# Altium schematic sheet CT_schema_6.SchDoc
size 287 x 160 mm
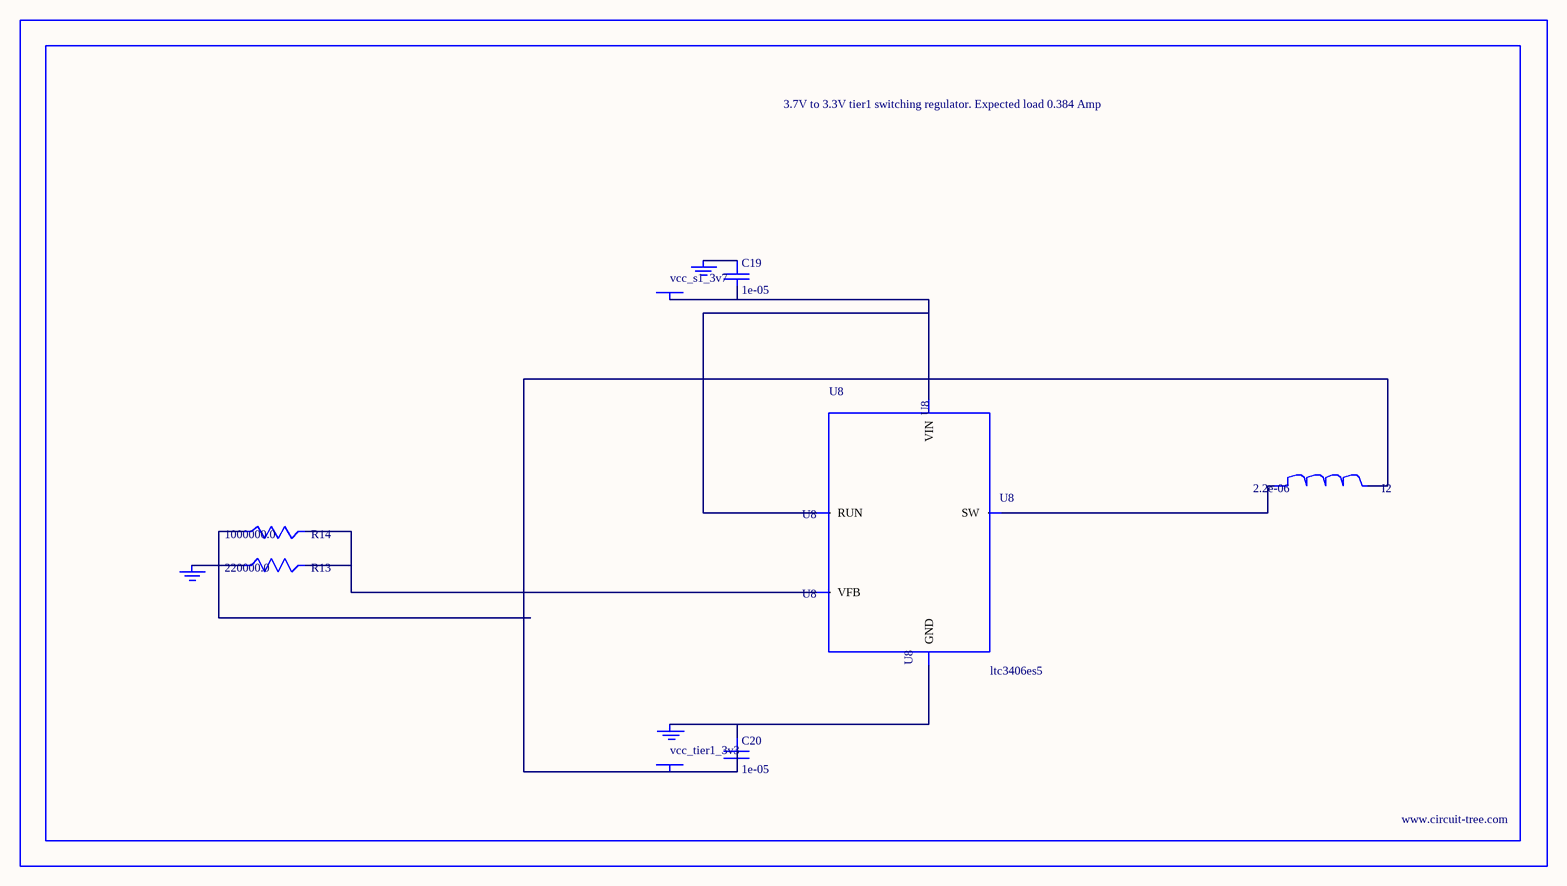
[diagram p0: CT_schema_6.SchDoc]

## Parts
BORDER5  (no value)
C19  1e-05  [C0805]
C20  1e-05  [C0805]
GND_INSTANCE_5_0  (no value)
GND_INSTANCE_5_1  (no value)
GND_INSTANCE_5_2  (no value)
I2  2.2e-06  [L0805]
POWER_INSTANCE_5_0  vcc_tier1_3v3
POWER_INSTANCE_5_1  vcc_s1_3v7
R13  220000.0  [R0603]
R14  1000000.0  [R0603]
U8  ltc3406es5  [TSOT-23-5]

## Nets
NetC19_1: C19.1 GND_INSTANCE_5_1.0(GND)
NetC19_2: C19.2 POWER_INSTANCE_5_1.0(PWR) U8.1(RUN) U8.4(VIN)
NetC20_1: C20.1 GND_INSTANCE_5_0.0(GND) U8.2(GND)
NetC20_2: C20.2 I2.2 POWER_INSTANCE_5_0.0(PWR) R14.1
NetGND_INSTANCE_5_2_0: GND_INSTANCE_5_2.0(GND) R13.1
NetI2_1: I2.1 U8.3(SW)
NetR13_2: R13.2 R14.2 U8.5(VFB)

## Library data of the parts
BORDER5 = BORDER_PAGE5
C19 C20 = C0805C106K8RACTU
GND_INSTANCE_5_0-GND_INSTANCE_5_2 = GND
I2 = L0805C2R2MDWIT
POWER_INSTANCE_5_0 POWER_INSTANCE_5_1 = PWR
R13 = RC0603JR-07220KL
R14 = RC0603JR-071ML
